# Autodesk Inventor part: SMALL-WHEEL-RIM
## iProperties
Created: 2007-08
Part Number: SMALL-WHEEL-RIM
Material: ABS Plastic
Document SubType Name: Modeling
Density: 1.06 g/cm^3
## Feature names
1. Base1
